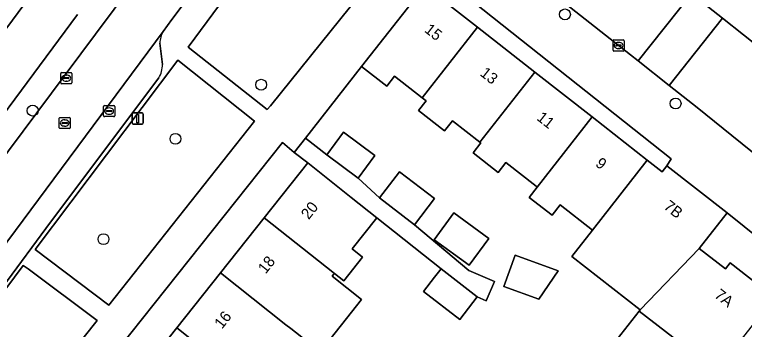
# Model space of a CAD drawing. Extents: x 160023 to 161302, y 384750 to 385707.
# Drawn here: x 160369 to 160434.7, y 385181.4 to 385209.8 of the extents above; entities that cross this region are included whole.
import ezdxf

# ---------------------------------------------------------------- set-up
doc = ezdxf.new("R2010")
doc.units = 0
for name, color, linetype in [('IMGEO_Boom', 7, 'Continuous'), ('IMGEO_Erf', 7, 'Continuous'), ('IMGEO_Groenvoorziening', 7, 'Continuous'), ('IMGEO_Kolk', 7, 'Continuous'), ('IMGEO_Lichtmast', 7, 'Continuous'), ('IMGEO_Muur', 7, 'Continuous'), ('IMGEO_Pand', 7, 'Continuous'), ('IMGEO_Pand_nummerreeks', 7, 'Continuous'), ('IMGEO_Parkeervlak_open', 7, 'Continuous'), ('IMGEO_Rijbaan_lokaal_gesloten', 7, 'Continuous'), ('IMGEO_Rijbaan_lokaal_open', 7, 'Continuous'), ('IMGEO_Rioolput', 7, 'Continuous'), ('IMGEO_Voetpad_open', 7, 'Continuous')]:
    doc.layers.add(name, color=color, linetype=linetype)

msp = doc.modelspace()

# ---------------------------------------------------------------- linework, layer by layer
at = {"layer": 'IMGEO_Boom'}
for centre in [(160418.501, 385209.777), (160391.159, 385203.454), (160428.46, 385201.761), (160370.593, 385201.125), (160383.447, 385198.584), (160376.968, 385189.559)]:
    msp.add_circle(centre, 0.489, dxfattribs=at)
at = {"layer": 'IMGEO_Erf'}
for points in [[(160428.067, 385196.779), (160406.896, 385213.577), (160405.877, 385212.35), (160410.618, 385208.637), (160415.785, 385204.591), (160420.945, 385200.549), (160425.913, 385196.659), (160427.254, 385195.608), (160427.68, 385196.151)], [(160383.571, 385181.582), (160387.503, 385186.537), (160391.428, 385191.482), (160395.345, 385196.418), (160394.128, 385197.351), (160393.08, 385198.252), (160361.551, 385158.668), (160363.901, 385156.796), (160367.765, 385161.665), (160371.683, 385166.602), (160375.621, 385171.564), (160379.56, 385176.528)], [(160406.745, 385189.506), (160408.502, 385191.921), (160411.652, 385189.628), (160409.894, 385187.213)], [(160439.384, 385186.88), (160433.087, 385191.917), (160430.594, 385188.734), (160432.942, 385186.896), (160433.368, 385187.44), (160437.348, 385184.323)], [(160413, 385185.287), (160414.014, 385188.108), (160417.878, 385186.718), (160416.165, 385184.149)]]:
    msp.add_lwpolyline(points, close=True, dxfattribs=at)
for points in [[(160374.284, 385210.782), (160372.389, 385212.172), (160371.43, 385212.869), (160367.649, 385207.769)], [(160325.028, 385142.851), (160374.618, 385209.767)], [(160421.23, 385178.051), (160425.168, 385183.079), (160425.265, 385183.203), (160419.135, 385188.004), (160420.983, 385190.364), (160418.071, 385192.644), (160417.341, 385191.712), (160415.286, 385193.321), (160416.005, 385194.24), (160415.912, 385194.313), (160413.181, 385196.453), (160412.488, 385195.569), (160410.233, 385197.335), (160410.931, 385198.226), (160410.851, 385198.289), (160408.391, 385200.216), (160407.671, 385199.298), (160405.332, 385201.13), (160406.009, 385201.994), (160405.642, 385202.281), (160403.159, 385204.226), (160402.459, 385203.333), (160400.2, 385205.102), (160395.146, 385198.65), (160397.062, 385197.144), (160398.574, 385199.178), (160401.397, 385197.08), (160399.884, 385195.046), (160401.801, 385193.265), (160403.614, 385195.625), (160406.764, 385193.206), (160404.951, 385190.846), (160409.849, 385186.755), (160412.165, 385185.762), (160411.415, 385184.013), (160410.613, 385184.383), (160409.034, 385182.339), (160405.775, 385184.856), (160406.774, 385186.149), (160407.354, 385186.899), (160401.57, 385191.478), (160399.358, 385188.692), (160400.293, 385187.95), (160398.587, 385185.8), (160397.745, 385186.468), (160397.672, 385186.376), (160397.549, 385186.221), (160400.187, 385184.128), (160396.458, 385179.43)]]:
    msp.add_lwpolyline(points, dxfattribs=at)
at = {"layer": 'IMGEO_Groenvoorziening'}
msp.add_lwpolyline([(160394.69, 385220.175), (160394.309, 385219.721), (160389.638, 385213.652), (160384.604, 385206.829), (160391.713, 385201.212), (160391.988, 385201.554), (160403.665, 385216.056)], dxfattribs=at)
for points in [[(160390.57, 385200.16), (160383.66, 385205.645), (160370.805, 385188.638), (160377.45, 385183.631)], [(160376.389, 385182.23), (160370.176, 385186.877), (160369.737, 385187.204), (160359.382, 385173.302), (160359.884, 385172.928), (160365.601, 385168.714)]]:
    msp.add_lwpolyline(points, close=True, dxfattribs=at)
at = {"layer": 'IMGEO_Kolk'}
for p, q in [((160422.827, 385206.556), (160422.827, 385207.408)), ((160422.902, 385207.482), (160423.754, 385207.482)), ((160423.315, 385207.262), (160423.34, 385207.262)), ((160423.828, 385207.408), (160423.828, 385206.556)), ((160423.086, 385206.976), (160423.086, 385206.988)), ((160423.524, 385206.939), (160423.126, 385206.939)), ((160423.129, 385207.025), (160423.527, 385207.025)), ((160423.338, 385206.702), (160423.313, 385206.702)), ((160423.57, 385206.988), (160423.57, 385206.976)), ((160423.754, 385206.482), (160422.902, 385206.482)), ((160373.194, 385204.545), (160374.046, 385204.545)), ((160373.119, 385203.619), (160373.119, 385204.471)), ((160373.378, 385204.039), (160373.378, 385204.051)), ((160373.816, 385204.002), (160373.418, 385204.002)), ((160373.421, 385204.088), (160373.819, 385204.088)), ((160373.607, 385204.325), (160373.632, 385204.325)), ((160373.862, 385204.051), (160373.862, 385204.039)), ((160374.12, 385204.471), (160374.12, 385203.619)), ((160374.046, 385203.545), (160373.194, 385203.545)), ((160373.63, 385203.765), (160373.605, 385203.765)), ((160376.978, 385200.652), (160376.978, 385201.504)), ((160377.053, 385201.578), (160377.905, 385201.578)), ((160377.466, 385201.358), (160377.491, 385201.358)), ((160377.979, 385201.504), (160377.979, 385200.652)), ((160377.237, 385201.072), (160377.237, 385201.084)), ((160377.675, 385201.035), (160377.277, 385201.035)), ((160377.28, 385201.121), (160377.678, 385201.121)), ((160377.489, 385200.798), (160377.464, 385200.798)), ((160377.721, 385201.084), (160377.721, 385201.072)), ((160377.905, 385200.578), (160377.053, 385200.578))]:
    msp.add_line(p, q, dxfattribs=at)
for points in [[(160422.827, 385206.556), (160422.827, 385207.408)], [(160422.902, 385207.482), (160423.754, 385207.482)], [(160423.828, 385207.408), (160423.828, 385206.556)], [(160423.754, 385206.482), (160422.902, 385206.482)], [(160373.194, 385204.545), (160374.046, 385204.545)], [(160373.119, 385203.619), (160373.119, 385204.471)], [(160374.12, 385204.471), (160374.12, 385203.619)], [(160374.046, 385203.545), (160373.194, 385203.545)], [(160376.978, 385200.652), (160376.978, 385201.504)], [(160377.053, 385201.578), (160377.905, 385201.578)], [(160377.979, 385201.504), (160377.979, 385200.652)], [(160377.905, 385200.578), (160377.053, 385200.578)]]:
    msp.add_lwpolyline(points, dxfattribs=at)
for centre, radius, start, end in [((160422.904, 385207.406), 0.0765, 91.55205, 178.44795), ((160422.904, 385207.406), 0.0765, 91.55205, 178.44795), ((160423.752, 385207.406), 0.0765, 1.55205, 88.44795), ((160423.752, 385207.406), 0.0765, 1.55205, 88.44795), ((160422.904, 385206.558), 0.0765, 181.55205, 268.44795), ((160422.904, 385206.558), 0.0765, 181.55205, 268.44795), ((160423.126, 385206.985), 0.0403, 85.87752, 175.75265), ((160423.123, 385206.975), 0.0366, 178.93798, 274.71019), ((160423.527, 385206.982), 0.043, 264.86636, 352.45326), ((160423.531, 385206.987), 0.0386, 1.73085, 96.63898), ((160423.752, 385206.558), 0.0765, 271.55205, 358.44795), ((160423.752, 385206.558), 0.0765, 271.55205, 358.44795), ((160373.196, 385204.469), 0.0765, 91.55205, 178.44795), ((160373.196, 385204.469), 0.0765, 91.55205, 178.44795), ((160374.044, 385204.469), 0.0765, 1.55205, 88.44795), ((160374.044, 385204.469), 0.0765, 1.55205, 88.44795), ((160373.418, 385204.048), 0.0403, 85.87752, 175.75265), ((160373.415, 385204.038), 0.0366, 178.93798, 274.71019), ((160373.819, 385204.045), 0.043, 264.86636, 352.45326), ((160373.823, 385204.05), 0.0386, 1.73085, 96.63898), ((160373.196, 385203.621), 0.0765, 181.55205, 268.44795), ((160373.196, 385203.621), 0.0765, 181.55205, 268.44795), ((160374.044, 385203.621), 0.0765, 271.55205, 358.44795), ((160374.044, 385203.621), 0.0765, 271.55205, 358.44795), ((160377.055, 385201.502), 0.0765, 91.55205, 178.44795), ((160377.055, 385201.502), 0.0765, 91.55205, 178.44795), ((160377.903, 385201.502), 0.0765, 1.55205, 88.44795), ((160377.903, 385201.502), 0.0765, 1.55205, 88.44795), ((160377.055, 385200.654), 0.0765, 181.55205, 268.44795), ((160377.055, 385200.654), 0.0765, 181.55205, 268.44795), ((160377.277, 385201.081), 0.0403, 85.87752, 175.75265), ((160377.274, 385201.071), 0.0366, 178.93798, 274.71019), ((160377.678, 385201.078), 0.043, 264.86636, 352.45326), ((160377.682, 385201.083), 0.0386, 1.73085, 96.63898), ((160377.903, 385200.654), 0.0765, 271.55205, 358.44795), ((160377.903, 385200.654), 0.0765, 271.55205, 358.44795)]:
    msp.add_arc(centre, radius, start, end, dxfattribs=at)
for centre, major_axis, ratio, start_param, end_param in [((160423.314, 385206.982), (-0.387, 0.002), 0.722429, 4.712389, 7.853982), ((160423.339, 385206.982), (-0.39, 0.002), 0.717154, 1.570796, 4.712389), ((160373.606, 385204.045), (-0.387, 0.002), 0.722429, 4.712389, 7.853982), ((160373.631, 385204.045), (-0.39, 0.002), 0.717154, 1.570796, 4.712389), ((160377.465, 385201.078), (-0.387, 0.002), 0.722429, 4.712389, 7.853982), ((160377.49, 385201.078), (-0.39, 0.002), 0.717154, 1.570796, 4.712389)]:
    msp.add_ellipse(centre, major_axis=major_axis, ratio=ratio, start_param=start_param, end_param=end_param, dxfattribs=at)
at = {"layer": 'IMGEO_Lichtmast'}
for p, q in [((160379.547, 385200.01), (160379.547, 385200.81)), ((160379.547, 385200.81), (160379.547, 385200.01)), ((160379.647, 385200.91), (160380.437, 385200.91)), ((160380.437, 385200.91), (160379.647, 385200.91)), ((160380.537, 385200.81), (160380.537, 385200.01)), ((160380.537, 385200.01), (160380.537, 385200.81)), ((160380.437, 385199.91), (160379.647, 385199.91)), ((160379.647, 385199.91), (160380.437, 385199.91))]:
    msp.add_line(p, q, dxfattribs=at)
msp.add_lwpolyline([(160379.967, 385200.785), (160380.117, 385200.785), (160380.117, 385200.035), (160379.967, 385200.035), (160379.967, 385200.785)], dxfattribs=at)
for centre, start, end in [((160379.647, 385200.81), 90, 180), ((160379.647, 385200.81), 90, 180), ((160380.437, 385200.81), 0, 90), ((160380.437, 385200.81), 360, 90), ((160379.647, 385200.01), 180, 270), ((160379.647, 385200.01), 180, 270), ((160380.437, 385200.01), 270, 0), ((160380.437, 385200.01), 270, 0)]:
    msp.add_arc(centre, 0.1, start, end, dxfattribs=at)
at = {"layer": 'IMGEO_Muur'}
msp.add_lwpolyline([(160400.2, 385205.102), (160395.146, 385198.65)], dxfattribs=at)
at = {"layer": 'IMGEO_Pand'}
for points in [[(160367.649, 385207.769), (160371.43, 385212.869), (160367.434, 385215.874), (160364.899, 385217.78), (160361.059, 385212.654)], [(160400.2, 385205.102), (160402.459, 385203.333), (160403.159, 385204.226), (160405.642, 385202.281), (160410.618, 385208.637), (160405.877, 385212.35)], [(160415.785, 385204.591), (160410.618, 385208.637), (160405.642, 385202.281), (160406.009, 385201.994), (160405.332, 385201.13), (160407.671, 385199.298), (160408.391, 385200.216), (160410.851, 385198.289)], [(160420.945, 385200.549), (160415.785, 385204.591), (160410.851, 385198.289), (160410.931, 385198.226), (160410.233, 385197.335), (160412.488, 385195.569), (160413.181, 385196.453), (160415.912, 385194.313), (160416.005, 385194.24)], [(160425.913, 385196.659), (160420.945, 385200.549), (160416.005, 385194.24), (160415.286, 385193.321), (160417.341, 385191.712), (160418.071, 385192.644), (160420.983, 385190.364)], [(160397.062, 385197.144), (160399.884, 385195.046), (160401.397, 385197.08), (160398.574, 385199.178)], [(160427.68, 385196.151), (160427.254, 385195.608), (160425.913, 385196.659), (160420.983, 385190.364), (160419.135, 385188.004), (160425.265, 385183.203), (160430.594, 385188.734), (160433.087, 385191.917)], [(160401.57, 385191.478), (160399.262, 385193.31), (160395.345, 385196.418), (160391.428, 385191.482), (160397.745, 385186.468), (160398.587, 385185.8), (160400.293, 385187.95), (160399.358, 385188.692)], [(160401.801, 385193.265), (160404.951, 385190.846), (160406.764, 385193.206), (160403.614, 385195.625)], [(160391.428, 385191.482), (160387.503, 385186.537), (160393.392, 385181.863), (160393.821, 385181.523), (160394.665, 385180.853), (160396.033, 385179.767), (160396.458, 385179.43), (160400.187, 385184.128), (160397.549, 385186.221), (160397.672, 385186.376), (160397.745, 385186.468)], [(160406.745, 385189.506), (160409.894, 385187.213), (160411.652, 385189.628), (160408.502, 385191.921)], [(160432.749, 385179.524), (160433.27, 385179.116), (160437.348, 385184.323), (160433.368, 385187.44), (160432.942, 385186.896), (160430.594, 385188.734), (160425.265, 385183.203), (160425.168, 385183.079), (160431.63, 385178.095)], [(160413, 385185.287), (160416.165, 385184.149), (160417.878, 385186.718), (160414.014, 385188.108)], [(160407.354, 385186.899), (160406.774, 385186.149), (160405.775, 385184.856), (160409.034, 385182.339), (160410.613, 385184.383)], [(160387.503, 385186.537), (160383.571, 385181.582), (160389.906, 385176.555), (160390.597, 385176.03), (160390.772, 385175.897), (160392.115, 385174.831), (160396.033, 385179.767), (160394.665, 385180.853), (160393.821, 385181.523), (160393.392, 385181.863)], [(160425.168, 385183.079), (160421.23, 385178.051), (160427.655, 385173.02), (160431.63, 385178.095)], [(160383.571, 385181.582), (160379.56, 385176.528), (160385.886, 385171.507), (160388.886, 385169.126), (160392.913, 385174.198), (160392.115, 385174.831), (160390.772, 385175.897), (160390.597, 385176.03), (160389.906, 385176.555)]]:
    msp.add_lwpolyline(points, close=True, dxfattribs=at)
at = {"layer": 'IMGEO_Parkeervlak_open'}
for points in [[(160382.334, 385208.244), (160338.119, 385148.731), (160337.805, 385148.31)], [(160382.268, 385205.275), (160382.041, 385207.186)], [(160341.816, 385150.156), (160342.909, 385151.604), (160351.745, 385163.449), (160367.915, 385185.269), (160372.205, 385191.078), (160381.943, 385204.063)]]:
    msp.add_lwpolyline(points, dxfattribs=at)
for centre, radius, start, end in [((160384.337, 385207.12), 2.297, 150.6919, 178.34928), ((160380.174, 385205.187), 2.096, 327.56819, 2.41015)]:
    msp.add_arc(centre, radius, start, end, dxfattribs=at)
at = {"layer": 'IMGEO_Rijbaan_lokaal_gesloten'}
for points in [[(160388.572, 385242.838), (160388.547, 385243.785), (160388.218, 385244.48), (160387.482, 385245.014), (160383.33, 385248.034), (160378.457, 385241.523), (160388.748, 385233.82), (160401.759, 385223.985), (160424.4, 385206.138), (160425.09, 385205.591), (160429.89, 385211.645), (160425.337, 385215.255), (160410.622, 385226.946), (160405.461, 385231.215)], [(160432.685, 385209.429), (160427.886, 385203.374), (160430.391, 385201.388), (160443.949, 385190.449), (160457.401, 385180.015), (160457.591, 385179.868), (160464.662, 385174.045), (160477.991, 385163.487), (160483.829, 385171.349)], [(160466.559, 385182.691), (160455.018, 385191.715), (160445.916, 385198.941), (160432.685, 385209.429)]]:
    msp.add_lwpolyline(points, dxfattribs=at)
at = {"layer": 'IMGEO_Rijbaan_lokaal_open'}
for points in [[(160389.791, 385226.135), (160376.256, 385207.995), (160364.435, 385192.191), (160353.385, 385177.257), (160342.6, 385162.805), (160333.448, 385150.481), (160328.079, 385143.273)], [(160382.334, 385208.244), (160383.113, 385209.309), (160388.76, 385216.851), (160393.378, 385222.996)], [(160332.549, 385141.299), (160337.805, 385148.31), (160338.119, 385148.731), (160382.334, 385208.244)]]:
    msp.add_lwpolyline(points, dxfattribs=at)
msp.add_lwpolyline([(160432.685, 385209.429), (160429.89, 385211.645), (160425.09, 385205.591), (160427.886, 385203.374)], close=True, dxfattribs=at)
at = {"layer": 'IMGEO_Rioolput'}
for p, q in [((160372.975, 385199.582), (160372.975, 385200.434)), ((160373.05, 385200.508), (160373.902, 385200.508)), ((160373.234, 385200.002), (160373.234, 385200.014)), ((160373.672, 385199.965), (160373.274, 385199.965)), ((160373.277, 385200.051), (160373.675, 385200.051)), ((160373.463, 385200.288), (160373.488, 385200.288)), ((160373.718, 385200.014), (160373.718, 385200.002)), ((160373.976, 385200.434), (160373.976, 385199.582)), ((160373.902, 385199.508), (160373.05, 385199.508)), ((160373.486, 385199.728), (160373.461, 385199.728))]:
    msp.add_line(p, q, dxfattribs=at)
for points in [[(160372.975, 385199.582), (160372.975, 385200.434)], [(160373.05, 385200.508), (160373.902, 385200.508)], [(160373.976, 385200.434), (160373.976, 385199.582)], [(160373.902, 385199.508), (160373.05, 385199.508)]]:
    msp.add_lwpolyline(points, dxfattribs=at)
for centre, radius, start, end in [((160373.052, 385200.432), 0.0765, 91.55205, 178.44795), ((160373.052, 385200.432), 0.0765, 91.55205, 178.44795), ((160373.274, 385200.011), 0.0403, 85.87752, 175.75265), ((160373.271, 385200.001), 0.0366, 178.93798, 274.71019), ((160373.675, 385200.008), 0.043, 264.86636, 352.45326), ((160373.679, 385200.013), 0.0386, 1.73085, 96.63898), ((160373.9, 385200.432), 0.0765, 1.55205, 88.44795), ((160373.9, 385200.432), 0.0765, 1.55205, 88.44795), ((160373.052, 385199.584), 0.0765, 181.55205, 268.44795), ((160373.052, 385199.584), 0.0765, 181.55205, 268.44795), ((160373.9, 385199.584), 0.0765, 271.55205, 358.44795), ((160373.9, 385199.584), 0.0765, 271.55205, 358.44795)]:
    msp.add_arc(centre, radius, start, end, dxfattribs=at)
for centre, major_axis, ratio, start_param, end_param in [((160373.462, 385200.008), (-0.387, 0.002), 0.722429, 4.712389, 7.853982), ((160373.487, 385200.008), (-0.39, 0.002), 0.717154, 1.570796, 4.712389)]:
    msp.add_ellipse(centre, major_axis=major_axis, ratio=ratio, start_param=start_param, end_param=end_param, dxfattribs=at)
at = {"layer": 'IMGEO_Voetpad_open'}
for points in [[(160405.461, 385231.215), (160410.622, 385226.946), (160425.337, 385215.255), (160429.89, 385211.645), (160432.685, 385209.429), (160445.916, 385198.941), (160455.018, 385191.715), (160466.559, 385182.691)], [(160328.079, 385143.273), (160333.448, 385150.481), (160342.6, 385162.805), (160353.385, 385177.257), (160364.435, 385192.191), (160376.256, 385207.995), (160389.791, 385226.135)], [(160443.949, 385190.449), (160430.391, 385201.388), (160427.886, 385203.374), (160425.09, 385205.591), (160424.4, 385206.138), (160401.759, 385223.985)], [(160396.479, 385220.92), (160393.378, 385222.996), (160388.76, 385216.851), (160383.113, 385209.309), (160382.334, 385208.244)], [(160397.79, 385220.538), (160403.665, 385216.056), (160406.896, 385213.577), (160428.067, 385196.779), (160427.68, 385196.151), (160433.087, 385191.917), (160439.384, 385186.88), (160444.893, 385182.062)], [(160393.08, 385198.252), (160394.128, 385197.351), (160395.146, 385198.65), (160400.2, 385205.102), (160405.877, 385212.35), (160406.896, 385213.577), (160403.665, 385216.056), (160391.988, 385201.554), (160391.713, 385201.212), (160384.604, 385206.829), (160389.638, 385213.652), (160394.309, 385219.721), (160394.69, 385220.175)], [(160374.618, 385209.767), (160325.028, 385142.851)], [(160382.041, 385207.186), (160382.268, 385205.275)], [(160381.943, 385204.063), (160372.205, 385191.078), (160367.915, 385185.269), (160351.745, 385163.449), (160342.909, 385151.604), (160341.816, 385150.156)], [(160341.039, 385132.915), (160360.564, 385157.429), (160361.551, 385158.668), (160393.08, 385198.252)]]:
    msp.add_lwpolyline(points, dxfattribs=at)
for points in [[(160370.805, 385188.638), (160383.66, 385205.645), (160390.57, 385200.16), (160377.45, 385183.631)], [(160401.801, 385193.265), (160399.884, 385195.046), (160397.062, 385197.144), (160395.146, 385198.65), (160394.128, 385197.351), (160395.345, 385196.418), (160399.262, 385193.31), (160401.57, 385191.478), (160407.354, 385186.899), (160410.613, 385184.383), (160411.415, 385184.013), (160412.165, 385185.762), (160409.849, 385186.755), (160404.951, 385190.846)], [(160365.601, 385168.714), (160359.884, 385172.928), (160359.382, 385173.302), (160369.737, 385187.204), (160370.176, 385186.877), (160376.389, 385182.23)]]:
    msp.add_lwpolyline(points, close=True, dxfattribs=at)
for centre, radius, start, end in [((160384.337, 385207.12), 2.297, 150.6919, 178.34928), ((160380.174, 385205.187), 2.096, 327.56819, 2.41015)]:
    msp.add_arc(centre, radius, start, end, dxfattribs=at)

# ---------------------------------------------------------------- texts
at = {"layer": 'IMGEO_Pand_nummerreeks'}
for s, rotation, p in [('15', 321.93407, (160405.78, 385208.259)), ('13', 321.93407, (160410.789, 385204.337)), ('11', 321.93268, (160415.888, 385200.344)), ('9', 321.93268, (160421.168, 385196.208)), ('20', 51.5662, (160395.437, 385191.258)), ('7B', 321.93696, (160427.318, 385192.36)), ('18', 51.5662, (160391.564, 385186.376)), ('7A', 321.93317, (160431.881, 385184.384)), ('16', 51.5662, (160387.631, 385181.421))]:
    msp.add_text(s, height=1, rotation=rotation, dxfattribs=at).set_placement(p)

doc.saveas('drawing.dxf')
